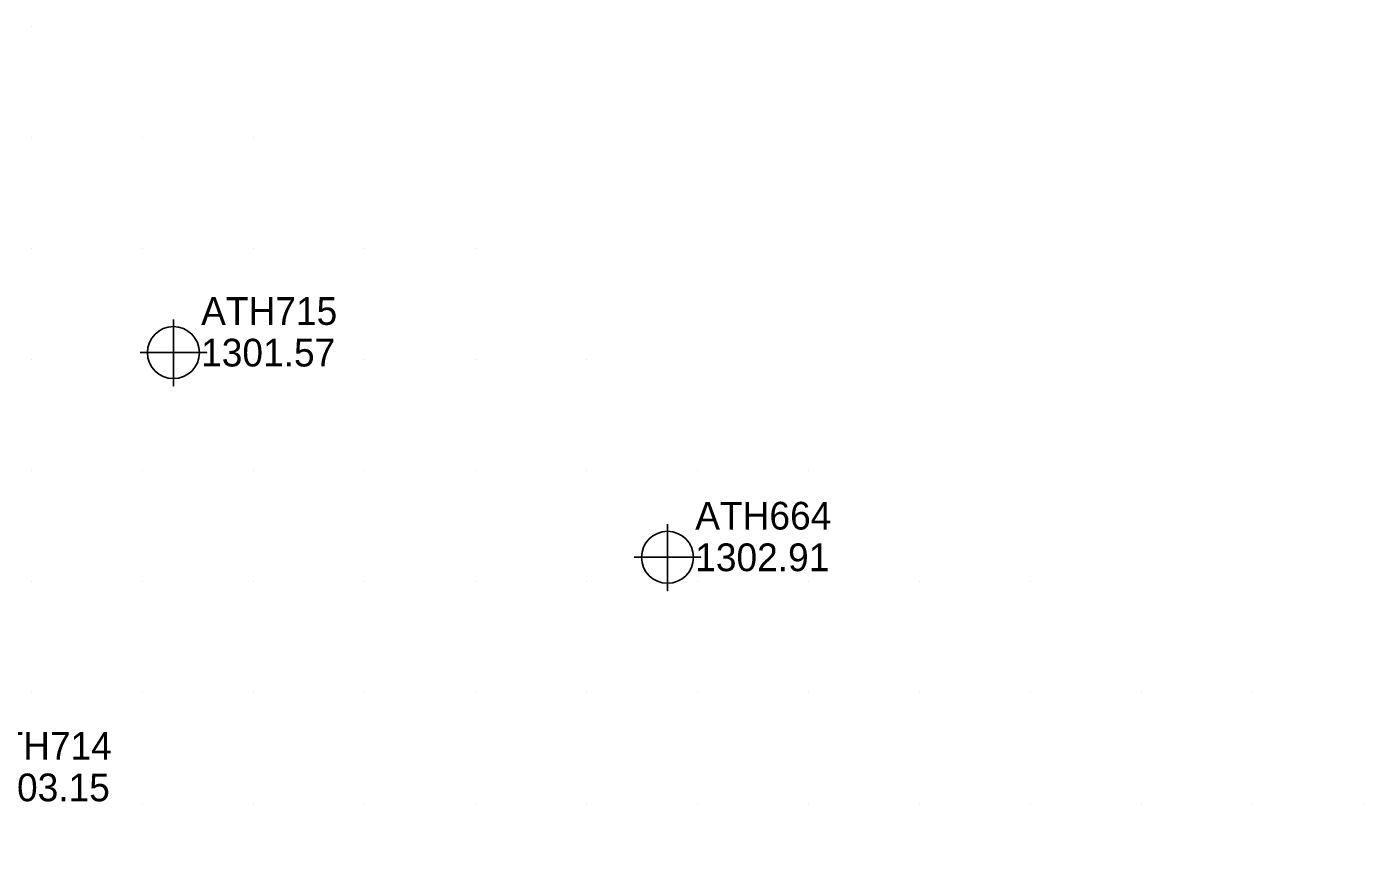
# Model space of a CAD drawing. Extents: x 1234484 to 1235382, y 695050 to 695510.
# Drawn here: x 1235159.5 to 1235280, y 695305.7 to 695380 of the extents above; entities that cross this region are included whole.
import ezdxf

# ---------------------------------------------------------------- set-up
doc = ezdxf.new("R2010")
doc.units = 0
for name, color, linetype in [('Exist DTM Crownline', 7, 'Continuous'), ('Exist DTM QL2 LIDAR Elevation Point', 7, 'Continuous'), ('Exist DTM Regular Point CELL', 7, 'Continuous'), ('Exist DTM Regular Point Cogo Elevation', 7, 'Continuous'), ('Exist DTM Regular Point Cogo Number', 7, 'Continuous'), ('Exist Roads EOP', 7, 'Continuous')]:
    doc.layers.add(name, color=color, linetype=linetype)

msp = doc.modelspace()

# ---------------------------------------------------------------- linework, layer by layer
at = {"layer": 'Exist DTM Crownline'}
msp.add_spline([(1234978.534, 695313.159), (1235028.867, 695302.317), (1235079.475, 695286.154), (1235130.202, 695265.942), (1235178.94, 695242.599), (1235226.8, 695217.474)], degree=3, dxfattribs=at)
at = {"layer": 'Exist DTM QL2 LIDAR Elevation Point'}
for p, q in [((1235160, 695380), (1235160, 695380)), ((1235160, 695370), (1235160, 695370)), ((1235170, 695370), (1235170, 695370)), ((1235180, 695370), (1235180, 695370)), ((1235160, 695360), (1235160, 695360)), ((1235170, 695360), (1235170, 695360)), ((1235180, 695360), (1235180, 695360)), ((1235190, 695360), (1235190, 695360)), ((1235200, 695360), (1235200, 695360)), ((1235160, 695350), (1235160, 695350)), ((1235170, 695350), (1235170, 695350)), ((1235180, 695350), (1235180, 695350)), ((1235190, 695350), (1235190, 695350)), ((1235200, 695350), (1235200, 695350)), ((1235210, 695350), (1235210, 695350)), ((1235160, 695340), (1235160, 695340)), ((1235170, 695340), (1235170, 695340)), ((1235180, 695340), (1235180, 695340)), ((1235190, 695340), (1235190, 695340)), ((1235200, 695340), (1235200, 695340)), ((1235210, 695340), (1235210, 695340)), ((1235220, 695340), (1235220, 695340)), ((1235230, 695340), (1235230, 695340)), ((1235160, 695330), (1235160, 695330)), ((1235170, 695330), (1235170, 695330)), ((1235180, 695330), (1235180, 695330)), ((1235190, 695330), (1235190, 695330)), ((1235200, 695330), (1235200, 695330)), ((1235210, 695330), (1235210, 695330)), ((1235220, 695330), (1235220, 695330)), ((1235230, 695330), (1235230, 695330)), ((1235240, 695330), (1235240, 695330)), ((1235250, 695330), (1235250, 695330)), ((1235160, 695320), (1235160, 695320)), ((1235170, 695320), (1235170, 695320)), ((1235180, 695320), (1235180, 695320)), ((1235190, 695320), (1235190, 695320)), ((1235200, 695320), (1235200, 695320)), ((1235210, 695320), (1235210, 695320)), ((1235220, 695320), (1235220, 695320)), ((1235230, 695320), (1235230, 695320)), ((1235240, 695320), (1235240, 695320)), ((1235250, 695320), (1235250, 695320)), ((1235260, 695320), (1235260, 695320)), ((1235270, 695320), (1235270, 695320)), ((1235160, 695310), (1235160, 695310)), ((1235170, 695310), (1235170, 695310)), ((1235180, 695310), (1235180, 695310)), ((1235190, 695310), (1235190, 695310)), ((1235200, 695310), (1235200, 695310)), ((1235210, 695310), (1235210, 695310)), ((1235220, 695310), (1235220, 695310)), ((1235230, 695310), (1235230, 695310)), ((1235240, 695310), (1235240, 695310)), ((1235250, 695310), (1235250, 695310)), ((1235260, 695310), (1235260, 695310)), ((1235270, 695310), (1235270, 695310)), ((1235280, 695310), (1235280, 695310))]:
    msp.add_line(p, q, dxfattribs=at)
at = {"layer": 'Exist DTM Regular Point CELL'}
for points in [[(1235172.761, 695353.621), (1235172.761, 695347.621), (1235172.761, 695350.621), (1235175.761, 695350.621), (1235169.761, 695350.621)], [(1235217.293, 695335.169), (1235217.293, 695329.169), (1235217.293, 695332.169), (1235220.293, 695332.169), (1235214.293, 695332.169)]]:
    msp.add_lwpolyline(points, dxfattribs=at)
for centre in [(1235172.761, 695350.621), (1235217.293, 695332.169)]:
    msp.add_circle(centre, 2.344, dxfattribs=at)
at = {"layer": 'Exist Roads EOP'}
msp.add_spline([(1234989.744, 695321.275), (1235032.632, 695310.758), (1235082.97, 695294.625), (1235134.247, 695274.482), (1235183.928, 695250.955), (1235232.115, 695225.68)], degree=3, dxfattribs=at)

# ---------------------------------------------------------------- texts
at = {"layer": 'Exist DTM Regular Point Cogo Elevation'}
for s, p in [('1301.57', (1235175.261, 695349.371)), ('1302.91', (1235219.793, 695330.919)), ('1303.15', (1235154.948, 695310.175))]:
    msp.add_text(s, height=2.5, dxfattribs=at).set_placement(p)
at = {"layer": 'Exist DTM Regular Point Cogo Number'}
for s, p in [('ATH715', (1235175.261, 695353.121)), ('ATH664', (1235219.793, 695334.669)), ('ATH714', (1235154.948, 695313.925))]:
    msp.add_text(s, height=2.5, dxfattribs=at).set_placement(p)

doc.saveas('drawing.dxf')
